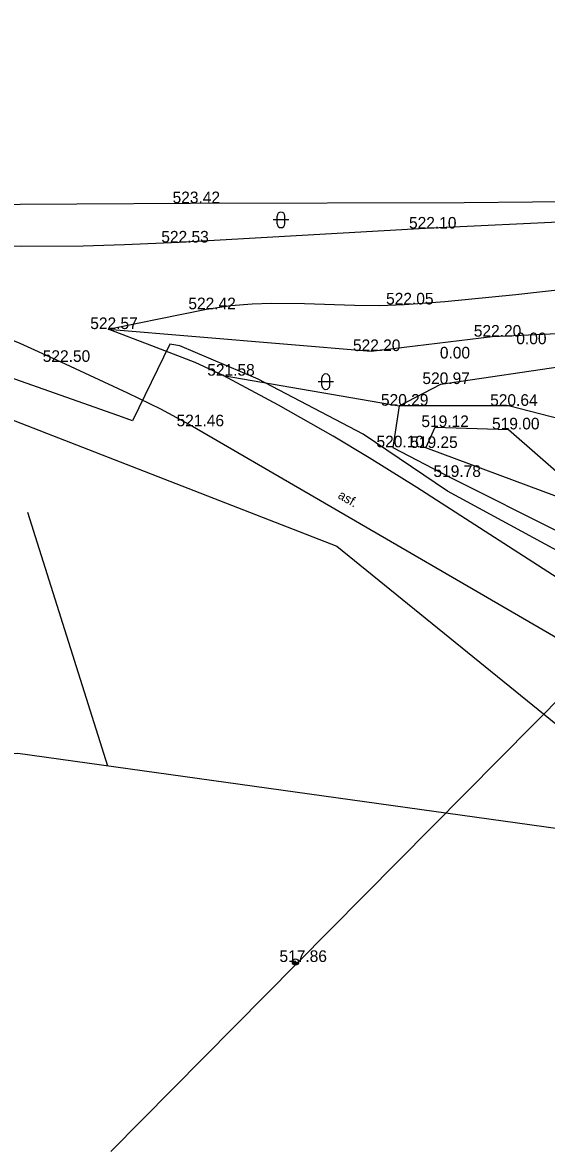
# Model space of a CAD drawing. Extents: x -669393 to -668650, y -1126925 to -1126294.
# Drawn here: x -668857.9 to -668824.1, y -1126886.2 to -1126813.3 of the extents above; entities that cross this region are included whole.
import ezdxf

# ---------------------------------------------------------------- set-up
doc = ezdxf.new("R2010")
doc.units = 0
for name, color, linetype in [('G_Bod_tecka', 7, 'Continuous'), ('G_Bod_vyska', 7, 'Continuous'), ('G_Breh_Teren', 7, 'Continuous'), ('G_Plochy_zpevnene', 7, 'Continuous'), ('G_Popisy_povrchu', 7, 'Continuous'), ('G_Site-Sloupy', 7, 'Continuous'), ('G_Z_CHRANICKA-TEPLOVOD_kotovane', 7, 'Continuous'), ('G_Z_ELsilove_nadz_kotovane', 7, 'Continuous'), ('G_Z_KANAL_podz_priblizne', 7, 'Continuous'), ('G_Z_SPOJE_podz_kotovane', 7, 'Continuous'), ('G_Zelen-Znacky', 7, 'Continuous'), ('Vrstva 18', 7, 'Continuous')]:
    doc.layers.add(name, color=color, linetype=linetype)

msp = doc.modelspace()

# ---------------------------------------------------------------- linework, layer by layer
at = {"layer": 'G_Bod_tecka'}
for p, q in [((-668847.08, -1126824.98), (-668847.08, -1126824.98)), ((-668831.92, -1126826.62), (-668831.92, -1126826.62)), ((-668847.81, -1126827.52), (-668847.81, -1126827.52)), ((-668846.05, -1126831.83), (-668846.05, -1126831.83)), ((-668833.26, -1126831.52), (-668833.26, -1126831.52)), ((-668852.39, -1126833.11), (-668852.39, -1126833.11)), ((-668827.59, -1126833.6), (-668827.59, -1126833.6)), ((-668825.24, -1126834.09), (-668825.24, -1126834.09)), ((-668835.39, -1126834.53), (-668835.39, -1126834.53)), ((-668830.19, -1126835.01), (-668830.19, -1126835.01)), ((-668855.45, -1126835.23), (-668855.45, -1126835.23)), ((-668844.97, -1126836.12), (-668844.97, -1126836.12)), ((-668830.9, -1126836.66), (-668830.9, -1126836.66)), ((-668833.58, -1126838.06), (-668833.58, -1126838.06)), ((-668826.52, -1126838.07), (-668826.52, -1126838.07)), ((-668846.95, -1126839.39), (-668846.95, -1126839.39)), ((-668831.27, -1126839.44), (-668831.27, -1126839.44)), ((-668826.53, -1126839.59), (-668826.53, -1126839.59)), ((-668834, -1126840.75), (-668834, -1126840.75)), ((-668831.86, -1126840.79), (-668831.86, -1126840.79)), ((-668830.36, -1126842.66), (-668830.36, -1126842.66)), ((-668840.29, -1126873.99), (-668840.29, -1126873.99))]:
    msp.add_line(p, q, dxfattribs=at)
at = {"layer": 'G_Breh_Teren'}
for p, q in [((-668827.59, -1126833.6), (-668811.93, -1126832.86)), ((-668852.39, -1126833.11), (-668835.39, -1126834.53)), ((-668835.39, -1126834.53), (-668827.59, -1126833.6)), ((-668830.9, -1126836.66), (-668817.55, -1126834.72)), ((-668844.97, -1126836.12), (-668833.58, -1126838.06)), ((-668833.58, -1126838.06), (-668830.9, -1126836.66)), ((-668833.58, -1126838.06), (-668834, -1126840.75)), ((-668826.52, -1126838.07), (-668833.58, -1126838.06)), ((-668816.39, -1126840.69), (-668826.52, -1126838.07)), ((-668831.86, -1126840.79), (-668831.27, -1126839.44)), ((-668831.27, -1126839.44), (-668826.53, -1126839.59)), ((-668826.53, -1126839.59), (-668820.21, -1126845.11)), ((-668834, -1126840.75), (-668830.36, -1126842.66)), ((-668820.21, -1126845.11), (-668831.86, -1126840.79)), ((-668830.36, -1126842.66), (-668823.06, -1126846.32))]:
    msp.add_line(p, q, dxfattribs=at)
msp.add_lwpolyline([(-668861.76, -1126825.07), (-668854.42, -1126825.02), (-668847.08, -1126824.98), (-668829.4, -1126824.94), (-668820.56, -1126824.84), (-668816.14, -1126824.73), (-668811.72, -1126824.57), (-668793.98, -1126823.82), (-668776.23, -1126823.06)], dxfattribs=at)
at = {"layer": 'G_Plochy_zpevnene'}
for points in [[(-668794.8, -1126825.6), (-668795.84, -1126825.39), (-668796.83, -1126825.24), (-668798.69, -1126825.06), (-668800.34, -1126825.01), (-668801.78, -1126825.02), (-668811.94, -1126825.73), (-668821.93, -1126826.15), (-668831.92, -1126826.62), (-668839.86, -1126827.06), (-668847.81, -1126827.52), (-668851.35, -1126827.68), (-668854.02, -1126827.75), (-668858.01, -1126827.77), (-668862, -1126827.68), (-668863.7, -1126827.58), (-668865.18, -1126827.44), (-668867.77, -1126827.06), (-668869.7, -1126826.68), (-668871.12, -1126826.34), (-668873.25, -1126825.74), (-668875.33, -1126825.04), (-668886.78, -1126820.88), (-668897.18, -1126817.23)], [(-668898.95, -1126821.9), (-668887.43, -1126826.31), (-668875.91, -1126830.71), (-668875.01, -1126831.01), (-668874.15, -1126831.24), (-668872.51, -1126831.53), (-668871.04, -1126831.69), (-668865.85, -1126831.96), (-668864.56, -1126832.08), (-668863.6, -1126832.21), (-668862.2, -1126832.5), (-668860.82, -1126832.92), (-668858.11, -1126834.02), (-668855.45, -1126835.23), (-668851.15, -1126837.23), (-668849.02, -1126838.26), (-668846.94, -1126839.39), (-668832.81, -1126847.59), (-668818.68, -1126855.79)], [(-668852.39, -1126833.11), (-668849.22, -1126832.47), (-668846.05, -1126831.83), (-668844.48, -1126831.58), (-668843.09, -1126831.47), (-668841.86, -1126831.43), (-668839.71, -1126831.46), (-668836.48, -1126831.56), (-668834.86, -1126831.58), (-668833.26, -1126831.52), (-668830.63, -1126831.32), (-668826.04, -1126830.87), (-668819.16, -1126830.1)], [(-668816.73, -1126853.39), (-668820.24, -1126851.2), (-668832.45, -1126843.34), (-668835.52, -1126841.43), (-668837.85, -1126840.03), (-668841.38, -1126838.02), (-668844.97, -1126836.12), (-668846.78, -1126835.28), (-668849.58, -1126834.19), (-668852.39, -1126833.11)]]:
    msp.add_lwpolyline(points, dxfattribs=at)
at = {"layer": 'G_Site-Sloupy'}
msp.add_circle((-668840.29, -1126873.99), 0.2, dxfattribs=at)
for radius in [0.18, 0.16, 0.14, 0.12, 0.1, 0.08, 0.06, 0.04, 0.02]:
    msp.add_arc((-668840.29, -1126873.99), radius, 180, 0, dxfattribs=at)
at = {"layer": 'G_Z_CHRANICKA-TEPLOVOD_kotovane'}
msp.add_lwpolyline([(-668847.77, -1126834.2), (-668848.41, -1126834.08), (-668850.82, -1126839.03), (-668851.48, -1126838.79)], dxfattribs=at)
at = {"layer": 'G_Z_ELsilove_nadz_kotovane'}
for points in [[(-668760.642, -1126791.685), (-668778.872, -1126810.991), (-668779.891, -1126812.071), (-668803.039, -1126836.585), (-668840.228, -1126874.108)], [(-668840.228, -1126874.108), (-668852.229, -1126886.228)]]:
    msp.add_lwpolyline(points, dxfattribs=at)
at = {"layer": 'G_Z_KANAL_podz_priblizne'}
msp.add_line((-668857.62, -1126844.93), (-668852.45, -1126861.32), dxfattribs=at)
for points in [[(-668885.68, -1126828.44), (-668837.62, -1126847.14), (-668813.42, -1126866.74)], [(-668886.5, -1126855.54), (-668866, -1126860.75), (-668858.24, -1126860.51), (-668813.42, -1126866.74)]]:
    msp.add_lwpolyline(points, dxfattribs=at)
at = {"layer": 'G_Z_SPOJE_podz_kotovane'}
msp.add_lwpolyline([(-668786.479, -1126876.427), (-668788.9, -1126874.54), (-668796.19, -1126867.69), (-668798.54, -1126865.87), (-668806.24, -1126859.05), (-668812.96, -1126854.08), (-668820.1, -1126849.2), (-668830.47, -1126843.58), (-668835.92, -1126839.89), (-668842.7, -1126836.35), (-668847.77, -1126834.2), (-668848.41, -1126834.08), (-668850.82, -1126839.03), (-668851.48, -1126838.79), (-668859.49, -1126835.98)], dxfattribs=at)
at = {"layer": 'G_Zelen-Znacky'}
for p, q in [((-668840.73, -1126826.06), (-668841.73, -1126826.06)), ((-668841.48, -1126826.31), (-668841.48, -1126825.81)), ((-668840.98, -1126826.31), (-668840.98, -1126825.81)), ((-668837.83, -1126836.51), (-668838.83, -1126836.51)), ((-668838.58, -1126836.76), (-668838.58, -1126836.26)), ((-668838.08, -1126836.76), (-668838.08, -1126836.26))]:
    msp.add_line(p, q, dxfattribs=at)
for centre, start, end in [((-668841.23, -1126825.81), 0, 180), ((-668841.23, -1126826.31), 180, 0), ((-668838.33, -1126836.26), 0, 180), ((-668838.33, -1126836.76), 180, 0)]:
    msp.add_arc(centre, 0.25, start, end, dxfattribs=at)
at = {"layer": 'Vrstva 18'}
msp.add_line((-668857.62, -1126844.93), (-668852.447, -1126861.318), dxfattribs=at)
msp.add_line((-668857.62, -1126844.93), (-668852.447, -1126861.318), dxfattribs=at)
for points in [[(-668885.68, -1126828.44), (-668837.62, -1126847.14), (-668813.42, -1126866.74)], [(-668885.68, -1126828.44), (-668837.62, -1126847.14), (-668813.42, -1126866.74)], [(-668886.5, -1126855.537), (-668866, -1126860.75), (-668858.241, -1126860.513), (-668813.42, -1126866.74)], [(-668886.5, -1126855.537), (-668866, -1126860.75), (-668858.241, -1126860.513), (-668813.42, -1126866.74)]]:
    msp.add_lwpolyline(points, dxfattribs=at)

# ---------------------------------------------------------------- texts
at = {"layer": 'G_Bod_vyska'}
for s, p in [('523.42', (-668848.234, -1126824.98)), ('522.10', (-668832.954, -1126826.62)), ('522.53', (-668848.964, -1126827.52)), ('522.05', (-668834.436, -1126831.52)), ('522.42', (-668847.214, -1126831.83)), ('522.57', (-668853.554, -1126833.11)), ('522.20', (-668828.766, -1126833.6)), ('0.00', (-668826.02, -1126834.09)), ('522.20', (-668836.576, -1126834.53)), ('0.00', (-668830.96, -1126835.01)), ('522.50', (-668856.626, -1126835.23)), ('521.58', (-668845.992, -1126836.12)), ('520.97', (-668832.088, -1126836.66)), ('520.29', (-668834.768, -1126838.06)), ('520.64', (-668827.709, -1126838.07)), ('521.46', (-668847.976, -1126839.39)), ('519.12', (-668832.153, -1126839.44)), ('519.00', (-668827.588, -1126839.59)), ('520.10', (-668835.056, -1126840.75)), ('519.25', (-668832.874, -1126840.79)), ('519.78', (-668831.374, -1126842.66)), ('517.86', (-668841.326, -1126873.99))]:
    msp.add_text(s, height=0.75, dxfattribs=at).set_placement(p)
at = {"layer": 'G_Popisy_povrchu'}
msp.add_text('asf.', height=0.6, rotation=329.87504, dxfattribs=at).set_placement((-668837.603, -1126844.002))

doc.saveas('drawing.dxf')
